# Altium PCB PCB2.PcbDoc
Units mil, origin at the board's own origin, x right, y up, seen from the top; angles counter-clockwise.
Board outline 2244.09 x 1732.28 mil, 4 copper layers (Top Layer, GND02, POWER03, Bottom Layer), stack 75.523 mil thick; 44 components, 99 nets, 307 pads, 120 vias.
Unrouted connection lines stored in the file: 48.
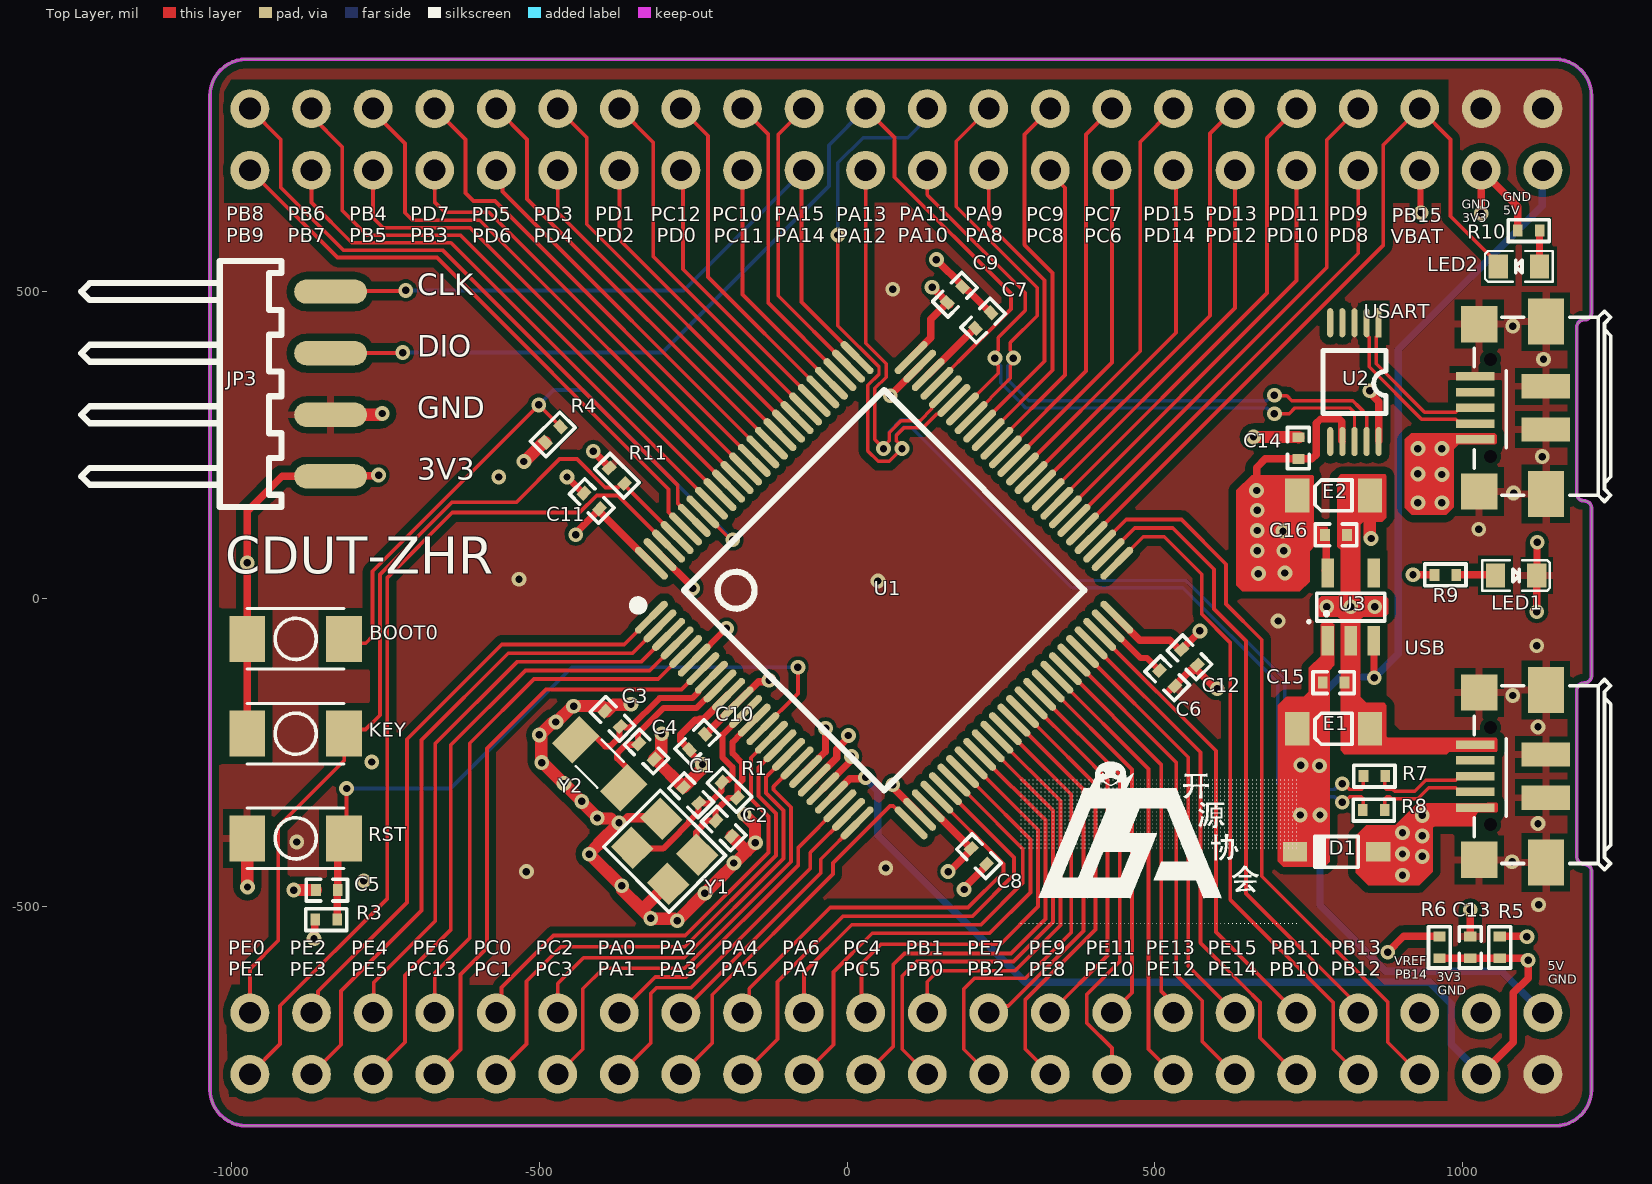
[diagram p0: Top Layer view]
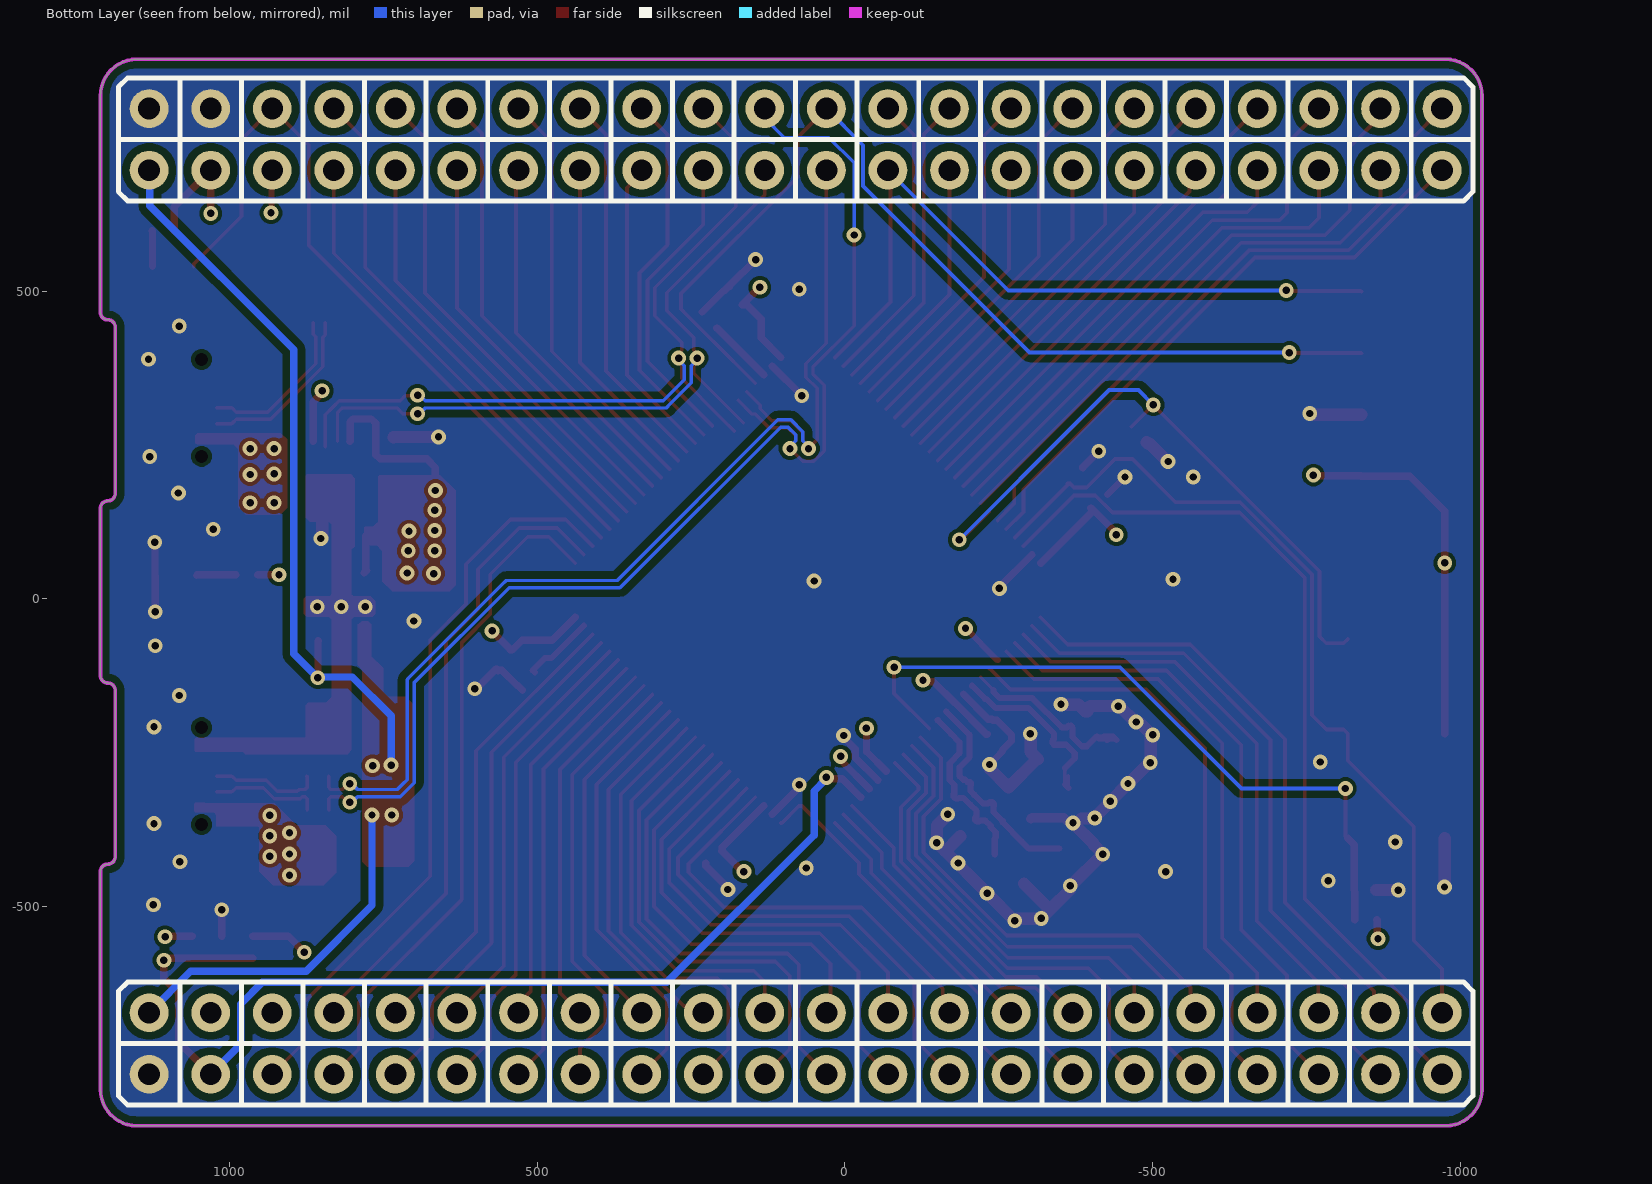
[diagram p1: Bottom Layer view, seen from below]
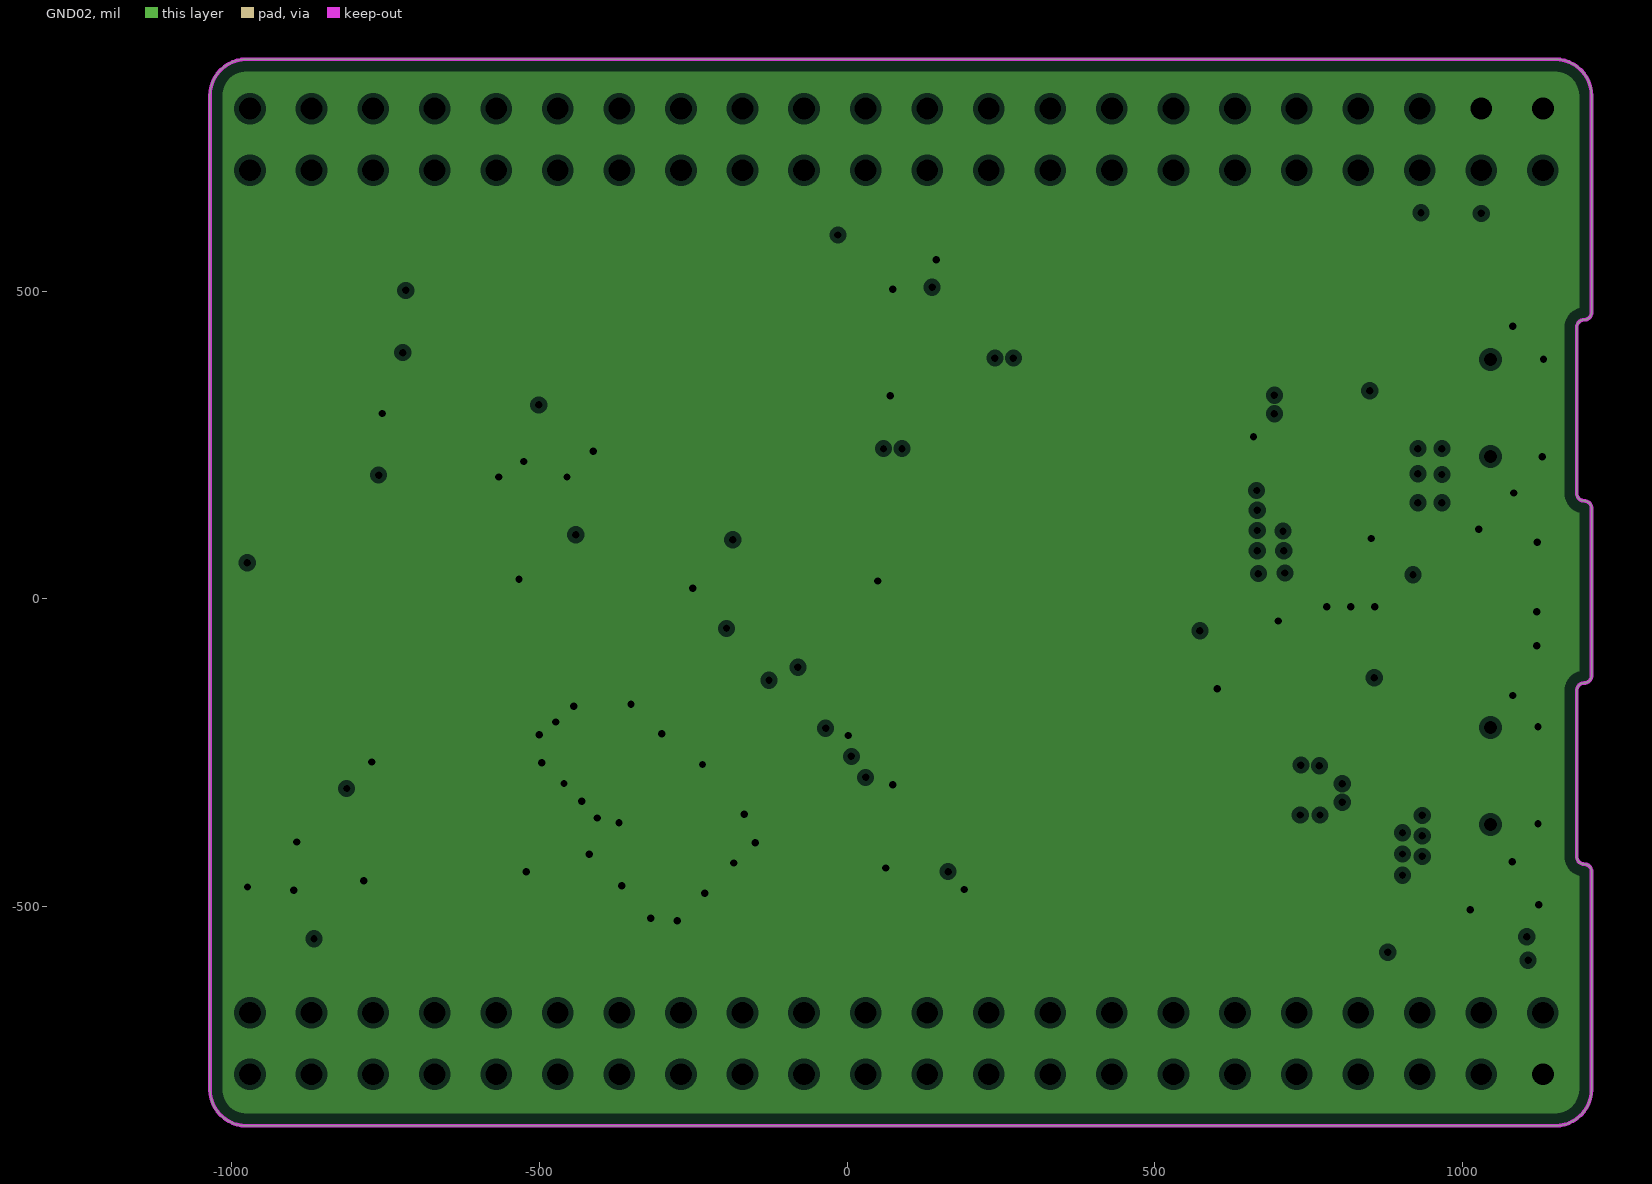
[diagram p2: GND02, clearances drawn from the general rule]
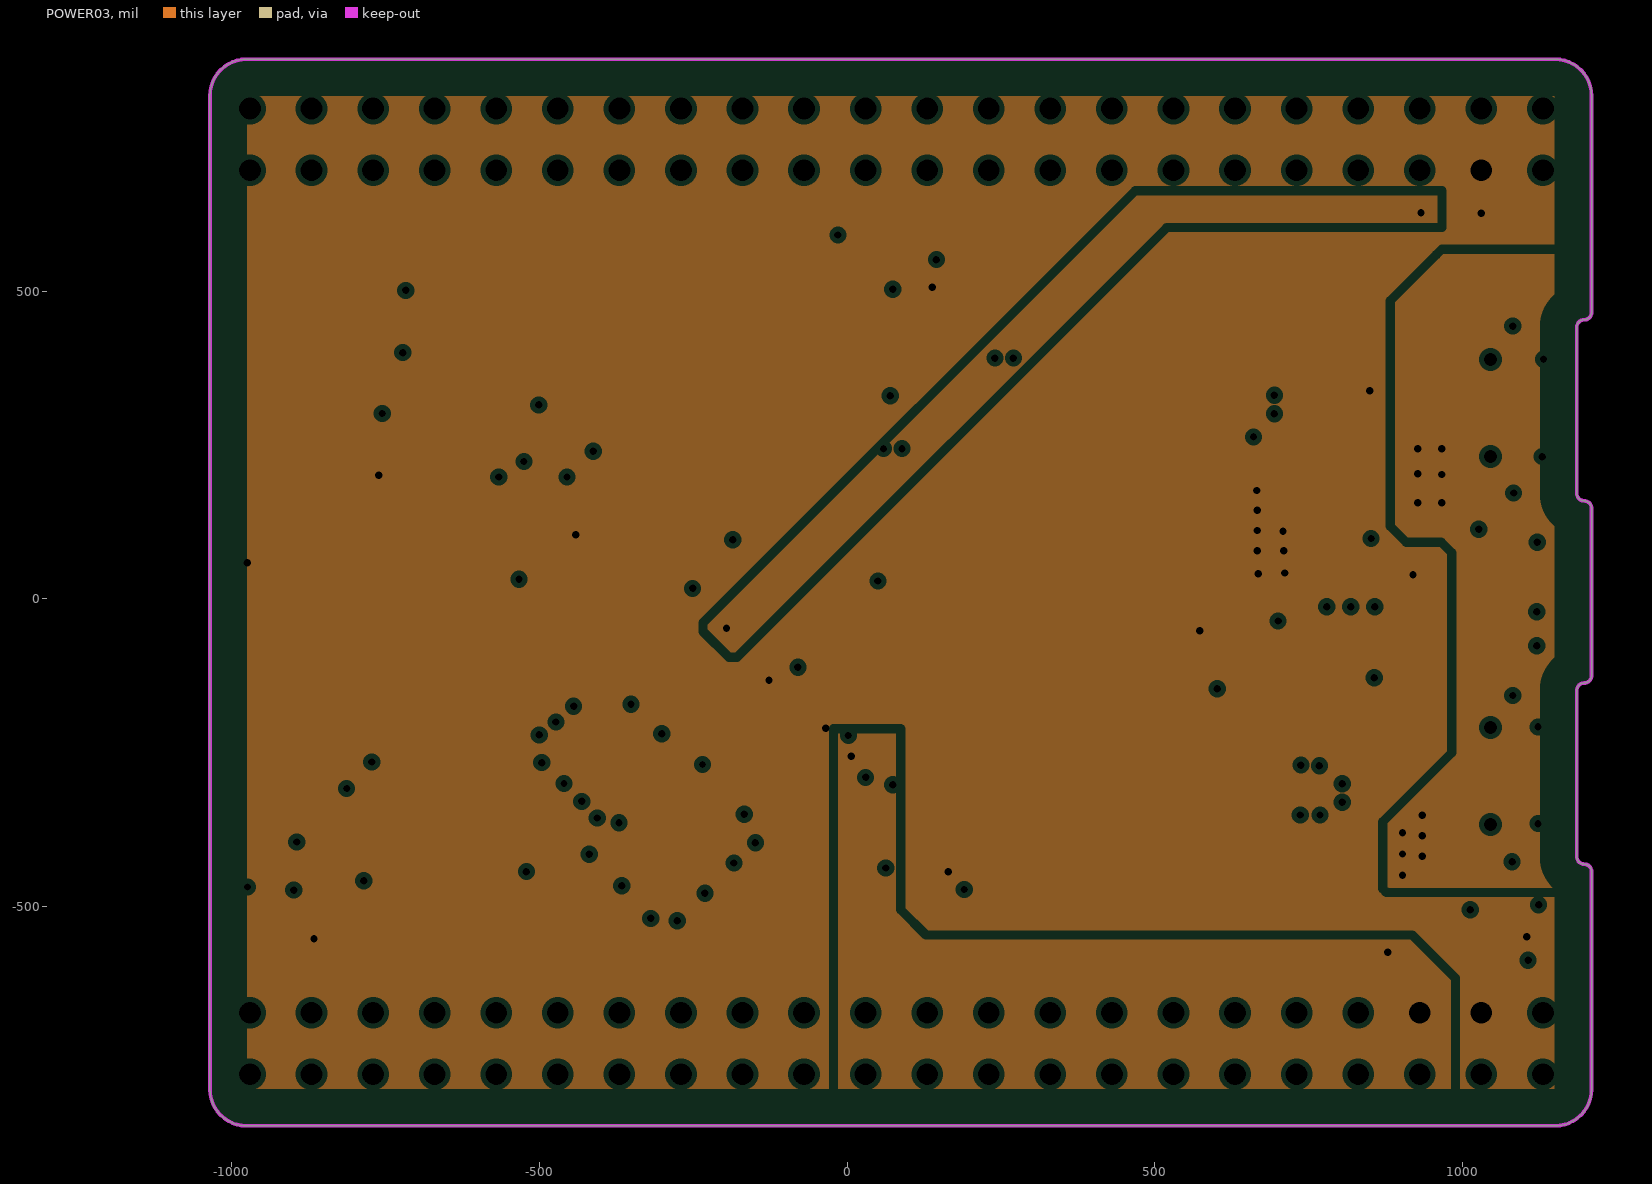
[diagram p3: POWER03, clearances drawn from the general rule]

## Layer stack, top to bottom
Top Solder: solder mask 0.4, Solder Resist, Dk 3.5
Top Layer: signal copper 1.38
Dielectric 2: prepreg 3.91, PP-015, Dk 4.3
GND02: plane copper 0.689, net GND
Dielectric 4: prepreg 2.8, PP-006, Dk 4.1
Dielectric 1: dielectric 2.8, FR-4, Dk 4.8
Dielectric 5: prepreg 2.8, PP-006, Dk 4.1
POWER03: plane copper 0.689, net (Multiple Nets)
Dielectric 3: prepreg 59.055, PP-006, Dk 4.1
Bottom Layer: signal copper 1.4
Bottom Solder: solder mask 0.4, Solder Resist, Dk 3.5

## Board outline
-1034.98,-796.8 ccw(c-975.92,-796.8) -975.93,-855.86 1150.06,-855.86 ccw(c1150.06,-796.8) 1209.11,-796.8 1209.11,-442.87 ccw(c1197.11,-442.87) 1197.11,-430.87 cw(c1197.11,-418.87) 1185.11,-418.87 1185.11,-148.71 cw(c1197.11,-148.71) 1197.11,-136.71 ccw(c1197.11,-124.71) 1209.11,-124.71 1209.11,147.13 ccw(c1197.11,147.13) 1197.11,159.13 cw(c1197.11,171.13) 1185.11,171.13 1185.11,441.29 cw(c1197.11,441.29) 1197.11,453.29 ccw(c1197.11,465.29) 1209.11,465.29 1209.11,817.37 ccw(c1150.06,817.37) 1150.06,876.43 -975.92,876.43 ccw(c-975.92,817.37) -1034.98,817.37

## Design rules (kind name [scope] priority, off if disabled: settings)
Clearance [All] p1: gap=6 ignorepadtopadclearanceinfootprint=FALSE except(12: Arc-Fill Arc-Poly Arc-Region Track-Fill Track-Poly Track-Region SMDPad-Fill SMDPad-Poly SMDPad-Region THPad-Fill THPad-Poly THPad-Region Fill-Fill Fill-Poly Fill-Region Poly-Poly Poly-Region Region-Region)
DiffPairsRouting DiffPair_DiffPairsRouting [All] p1: maxlimit=6 minlimit=6 mostfreqgap=6 toplayer_minwidth=5.59 toplayer_maxwidth=10 toplayer_prefwidth=5.59 bottomlayer_minwidth=5.59 bottomlayer_maxwidth=10 bottomlayer_prefwidth=5.59 maxuncoupledlength=500
DiffPairsRouting [All] p2: maxlimit=10 minlimit=10 mostfreqgap=10 toplayer_minwidth=15 toplayer_maxwidth=15 toplayer_prefwidth=15 bottomlayer_minwidth=15 bottomlayer_maxwidth=15 bottomlayer_prefwidth=15 maxuncoupledlength=500
Height [All] p1: minheight=0 maxheight=5000 prefheight=1000
MatchedLengths DiffPair_MatchedLengths [All] p1: tolerance=1000 checknetsindiffpair=FALSE checkdiffpairvsdiffpair=TRUE checkxsignals=TRUE checkothers=TRUE
PlaneClearance [All] p1: clearance=8
PlaneConnect [All] p1: pad.planeconnectstyle=Relief pad.reliefexpansion=12 pad.reliefentries=4 pad.reliefconductorwidth=10 pad.reliefairgap=8 via.planeconnectstyle=Direct via.reliefexpansion=20 via.reliefentries=4 via.reliefconductorwidth=10 via.reliefairgap=10
PolygonConnect [All] p1: thpad.connectstyle=Direct thpad.reliefconductorwidth=10 thpad.reliefentries=4 thpad.polygonreliefangle="90 Angle" thpad.airgapwidth=10 smdpad.connectstyle=Relief smdpad.reliefconductorwidth=12 smdpad.reliefentries=4 smdpad.polygonreliefangle="90 Angle" smdpad.airgapwidth=10 via.connectstyle=Direct via.reliefconductorwidth=10 via.reliefentries=4 via.polygonreliefangle="90 Angle" via.airgapwidth=10
RoutingVias [All] p1: holewidth=12 width=24 viastyle="Through Hole" minholewidth=12 minwidth=24 maxholewidth=12 maxwidth=24
SilkToSilkClearance [All] p1: silktosilkclearance=0
SilkToSolderMaskClearance [IsPad] p1: minsilkscreentomaskgap=4 clearancetoexposedcopper=TRUE
SolderMaskExpansion [All] p1: expansion=4 istentingtop=FALSE
SupplyNets "Schematic Supply Nets_3" [InNet('VCC')] p1: voltage=0.000
SupplyNets "Schematic Supply Nets_2" [InNet('3V3')] p2: voltage=0.000
SupplyNets "Schematic Supply Nets_1" [InNet('5V')] p3: voltage=0.000
SupplyNets "Schematic Supply Nets" [InNet('GND')] p4: voltage=0.000
UnRoutedNet [All] p1: checkbadconnections=TRUE
Width Width_power [InNetClass('power')] p1: maxlimit=100 minlimit=10 preferedwidth=12
Width [All] p2: maxlimit=100 minlimit=6.16 preferedwidth=6.16
23 further rules are at their usual default settings.

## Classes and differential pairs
net class power: 3V3 5V GND NetLED1_1 NetLED2_1 VBAT VCAP_1 VCAP_2 VCC VDDA VREF+
component class U_03-KEY+LED+SWD: BOOT0 C5 JP3 KEY LED1 LED2 R3 R4 R9 R10 R11 RST
component class U_02-CPU+Connect: C1 C2 C3 C4 C6 C7 C8 C9 C10 C11 C12 C13 R1 R5 R6 Y1 Y2
component class U_01-POWER: C14 C15 C16 D1 E1 E2 R8 U2 U3 USART USB
differential pair NewDifferentialPair6: +PA9 -PA10
differential pair NewDifferentialPair5: +PA11 -PA12
differential pair NewDifferentialPair4: +NetU2_1 -NetU2_2
differential pair NewDifferentialPair3: +NetR7_1 -NetR8_1
differential pair NewDifferentialPair2: +PH0 -PH1
differential pair NewDifferentialPair1: +PC14 -PC15

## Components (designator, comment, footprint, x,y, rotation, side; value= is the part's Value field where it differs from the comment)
BOOT0 "KEY" SWT3*4 -895.74,-65 r180 top (schematic designator KEY2)
C1 "20pF" "C 0402_L" -253.43,-318.89 r315 top
C2 "20pF" "C 0402_L" -200.43,-372.89 r135 top
C3 "10pF" "C 0402_L" -381,-195 r315 top
C4 "10pF" "C 0402_L" -326,-248 r135 top
C5 "0.1uF" "C 0402_L" -845,-473 r0 top
C6 "2.2uF" "C 0402_L" 520,-129 r135 top
C7 "2.2uF" "C 0402_L" 221,452 r225 top
C8 "0.1uF" "C 0402_L" 214,-418 r315 top
C9 "0.1uF" "C 0402_L" 175,494 r45 top
C10 "0.1uF" "C 0402_L" -243.53,-232.53 r225 top
C11 "0.1uF" "C 0402_L" -415,159 r135 top
C12 "0.1uF" "C 0402_L" 556,-95 r315 top
C13 "0.1uF" "C 0402_L" 1012,-566 r270 top
C14 "0.1uF" "C 0402_L" 733,245 r270 top
C15 "0.1uF" "C 0402_L" 790,-136 r180 top
C16 "0.1uF" "C 0402_L" 794,104 r180 top
D1 "1N4007" SOD-123 795,-411 r180 top
E1 "10uF" "CD A(3216)" 790,-211 r0 top
E2 "10uF" "CD A(3216)" 790,168 r0 top
JP1 "Header 2x22" HDR2.54-LI-2X22P 80,746.28 r180 top
JP2 "Header 2x22" HDR2.54-LI-2X22P 80,-722.22 r180 top
JP3 "SWD" HDR2.54-WS-4P -839,349 r90 top
KEY "KEY" SWT3*4 -895.74,-219 r180 top (schematic designator KEY3)
LED1 "LED" "LED 0603" 1086.46,38 r0 top
LED2 "LED" "LED 0603" 1091,540 r180 top
R1 "1M" "R 0402_L" -190.9,-310.42 r315 top
R3 "10K" "R 0402_L" -846,-521 r0 top
R4 "10K" "R 0402_L" -478,267 r45 top
R5 "0R" "R 0402_L" 1060,-566 r90 top
R6 "0R" "R 0402_L" 962,-566 r90 top
R7 "0R" "R 0402_L" 856.28,-288 r180 top
R8 "0R" "R 0402_L" 855.28,-343 r180 top
R9 "4.7K" "R 0402_L" 971.72,39 r0 top
R10 "4.7K" "R 0402_L" 1107,598 r0 top
R11 "10K" "R 0402_L" -374,200 r315 top
RST "KEY" SWT3*4 -895.74,-389 r180 top (schematic designator KEY1)
U1 "STM32F407VET6" "LQFP100 14X14_N" 60,14 r315 top
U2 "CH340E" MSOP10_L 824,352 r180 top
U3 "RT9013-33" SOT23-5N 817.94,-13 r0 top
USART "USB" USB-MICRO_E 1135,310.26 r90 top (schematic designator USB1)
USB "USB" USB-MICRO_E 1135,-288 r90 top (schematic designator USB2)
Y1 "8M" "OSC 3225-4P" -296.43,-409.89 r315 top
Y2 "32.768KHz" FC135-3.2X1.5 -402,-268 r315 top

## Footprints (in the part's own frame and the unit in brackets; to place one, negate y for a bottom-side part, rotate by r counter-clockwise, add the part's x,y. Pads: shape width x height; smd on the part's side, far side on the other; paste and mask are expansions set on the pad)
"C 0402_L" [mm] "无极性贴片电容"
  rect 0.4x0.5 smd: 1(-0.45,0) 2(0.45,0)
  silkscreen extent -0.85,-0.45 0.85,0.45, body extent -0.5,-0.26 0.5,0.26, height 0.53
"CD A(3216)" [mm] "长3.2mm，宽1.6mm，厚1.6mm"
  rect 1x1.4 smd: 1(-1.5,0) 2(1.5,0)
  silkscreen extent -0.76,-0.64 0.76,0.64, body extent -1.6,-0.8 1.6,0.8, height 1.6
FC135-3.2X1.5 [mm] "晶振"
  rect 1.2x1.6 smd: 1(-1.4,0) 2(1.4,0)
  silkscreen extent -0.64,-0.76 0.64,0.76, body extent -1.61,-0.76 1.61,0.76, height 0.91
HDR2.54-LI-2X22P [mm] "双排排针，20x2脚"
  round 1.6 hole 0.9: 1(-26.67,-1.27) 2(-26.67,1.27) 3(-24.13,-1.27) 4(-24.13,1.27) 5(-21.59,-1.27) 6(-21.59,1.27) 7(-19.05,-1.27) 8(-19.05,1.27) 9(-16.51,-1.27) 10(-16.51,1.27) 11(-13.97,-1.27) 12(-13.97,1.27) 13(-11.43,-1.27) 14(-11.43,1.27) 15(-8.89,-1.27) 16(-8.89,1.27) 17(-6.35,-1.27) 18(-6.35,1.27) 19(-3.81,-1.27) 20(-3.81,1.27) 21(-1.27,-1.27) 22(-1.27,1.27) 23(1.27,-1.27) 24(1.27,1.27) 25(3.81,-1.27) 26(3.81,1.27) 27(6.35,-1.27) 28(6.35,1.27) 29(8.89,-1.27) 30(8.89,1.27) 31(11.43,-1.27) 32(11.43,1.27) 33(13.97,-1.27) 34(13.97,1.27) 35(16.51,-1.27) 36(16.51,1.27) 37(19.05,-1.27) 38(19.05,1.27) 39(21.59,-1.27) 40(21.59,1.27) 41(24.13,-1.27) 42(24.13,1.27) 43(26.67,-1.27) 44(26.67,1.27)
  body extent -27.94,-2.54 27.94,2.54, height 8.5
HDR2.54-WS-4P [mm] "4P卧式贴片排针2.54"
  oval 1x3 smd: 1(-3.81,0) 2(-1.27,0) 3(1.27,0) 4(3.81,0)
  silkscreen extent -5.08,2.03 5.08,10.29, body extent -5.08,-0.76 5.08,10.34, height 2.54
"LED 0603" [mm] "贴片带丝印"
  rect 0.8x1 smd: 1(-0.85,0) 2(0.85,0)
  silkscreen extent -1.4,-0.64 1.4,0.64, body extent -0.8,-0.4 0.8,0.4, height 0.61
"LQFP100 14X14_N" [mm] "100脚，体宽14x14mm，脚距0.5mm"
  oval 0.3x1.8 smd: 1(-6,-7.575) 2(-5.5,-7.575) 3(-5,-7.575) 4(-4.5,-7.575) 5(-4,-7.575) 6(-3.5,-7.575) 7(-3,-7.575) 8(-2.5,-7.575) 9(-2,-7.575) 10(-1.5,-7.575) 11(-1,-7.575) 12(-0.5,-7.575) 13(0,-7.575) 14(0.5,-7.575) 15(1,-7.575) 16(1.5,-7.575) 17(2,-7.575) 18(2.5,-7.575) 19(3,-7.575) 20(3.5,-7.575) 21(4,-7.575) 22(4.5,-7.575) 23(5,-7.575) 24(5.5,-7.575) 25(6,-7.575) 51(6,7.575) 52(5.5,7.575) 53(5,7.575) 54(4.5,7.575) 55(4,7.575) 56(3.5,7.575) 57(3,7.575) 58(2.5,7.575) 59(2,7.575) 60(1.5,7.575) 61(1,7.575) 62(0.5,7.575) 63(0,7.575) 64(-0.5,7.575) 65(-1,7.575) 66(-1.5,7.575) 67(-2,7.575) 68(-2.5,7.575) 69(-3,7.575) 70(-3.5,7.575) 71(-4,7.575) 72(-4.5,7.575) 73(-5,7.575) 74(-5.5,7.575) 75(-6,7.575)
  oval 1.8x0.3 smd: 26(7.576,-6) 27(7.576,-5.5) 28(7.576,-5) 29(7.576,-4.5) 30(7.576,-4) 31(7.576,-3.5) 32(7.576,-3) 33(7.576,-2.5) 34(7.576,-2) 35(7.576,-1.5) 36(7.576,-1) 37(7.576,-0.5) 38(7.576,0) 39(7.576,0.5) 40(7.576,1) 41(7.576,1.5) 42(7.576,2) 43(7.576,2.5) 44(7.576,3) 45(7.576,3.5) 46(7.576,4) 47(7.576,4.5) 48(7.576,5) 49(7.576,5.5) 50(7.576,6) 76(-7.575,6) 77(-7.575,5.5) 78(-7.575,5) 79(-7.575,4.5) 80(-7.575,4) 81(-7.575,3.5) 82(-7.575,3) 83(-7.575,2.5) 84(-7.575,2) 85(-7.575,1.5) 86(-7.575,1) 87(-7.575,0.5) 88(-7.575,0) 89(-7.575,-0.5) 90(-7.575,-1) 91(-7.575,-1.5) 92(-7.575,-2) 93(-7.575,-2.5) 94(-7.575,-3) 95(-7.575,-3.5) 96(-7.575,-4) 97(-7.575,-4.5) 98(-7.575,-5) 99(-7.575,-5.5) 100(-7.575,-6)
  silkscreen extent -6.92,-7.81 5.84,5.84, body extent -8,-8 8,8, height 1.45
MSOP10_L [mm] "塑封体长3mm，宽3mm，脚距0.5"
  rect 0.25x1.2 smd: 1(-1,-2.45)
  oval 0.25x1.2 smd: 2(-0.5,-2.45) 3(0,-2.45) 4(0.5,-2.45) 5(1,-2.45) 6(1,2.45) 7(0.5,2.45) 8(0,2.45) 9(-0.5,2.45) 10(-1,2.45)
  silkscreen extent -1.3,-1.3 1.3,1.3, body extent -1.5,-2.45 1.5,2.45, height 0.95
"OSC 3225-4P" [mm] "3.2*2.5*0.7mm(长宽高)"
  rect 1.3x1.2 smd: 1(-1.05,-0.85) 2(1.05,-0.85) 3(1.05,0.85) 4(-1.05,0.85)
  silkscreen extent -1.9,-1.65 1.9,1.65, body extent -1.6,-1.25 1.6,1.25, height 0.7
"R 0402_L" [mm] "1/16W贴片电阻"
  rect 0.4x0.5 smd: 1(-0.45,0) 2(0.45,0)
  silkscreen extent -0.85,-0.45 0.85,0.45, body extent -0.5,-0.25 0.5,0.25, height 0.3
SOD-123 [mm] "2.7x1.6X1.1mm（长宽高，不包括引脚）"
  rect 1x0.8 smd: 1(-1.714,0) 2(1.714,0)
  silkscreen extent -0.89,-0.64 0.89,0.64, body extent -1.85,-0.8 1.85,0.8, height 1.22
SOT23-5N [mm] "3x1.6x1.1mm(长宽高)"
  rect 0.5x1.2 smd: 1(-0.95,-1.4) 2(0,-1.4) 3(0.95,-1.4) 4(0.95,1.4) 5(-0.95,1.4)
  silkscreen extent -1.4,-0.58 1.4,0.56, body extent -1.45,-1.4 1.45,1.4, height 1.2
SWT3*4 [mm]
  rect 1.48x1.9 smd: 1(-2,0) 2(2,0)
  silkscreen extent -2,-1.25 2,1.25, body extent -2.45,-1.45 2.45,1.45, height 2
USB-MICRO_E [mm] "micro型USB ，5.9*8.2*2.5mm"
  round 0 hole 0.54 unplated: 0(-2,2.294) 0(2,2.294)
  rect 0.35x1.6 smd: 1(-1.295,2.921) 2(-0.648,2.921) 3(0,2.921) 4(0.648,2.921) 5(1.295,2.921)
  rect 1.9x1.5 smd: 5(-3.556,0) 5(3.556,0)
  rect 1.5x1.5 smd: 5(-3.454,2.754) 5(3.454,2.754)
  rect 1x2 smd: 5(-0.889,0.01) 5(0.889,0.01)
  silkscreen extent -3.86,-2.67 3.99,2.96, body extent -4,-2.72 4,3.36, height 2.8

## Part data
C1 C2 C3 C4 C5 C6 C7 C8 C9 C10 C11 C12 C13 C14 C15 C16: library part Cap
D1: "整流二极管"
E1 E2: library part C-CD, "贴片钽电容"
JP1 JP2: "2x22P接插件"
JP3: library part "Header 1*4"
R1 R3 R4 R5 R6 R7 R8 R9 R10 R11: library part Res
U1: BOM_Manufacturer=ST
Y1: library part XTAL-4P, "4脚无源晶振"
Y2: library part XTAL-2P

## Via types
v1: diameter 24, hole 12, Top Layer to Bottom Layer, 120 vias

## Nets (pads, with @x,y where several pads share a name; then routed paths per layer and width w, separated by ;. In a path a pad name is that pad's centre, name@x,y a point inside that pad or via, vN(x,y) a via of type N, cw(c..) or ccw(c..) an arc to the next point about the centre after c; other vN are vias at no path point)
3V3: BOOT0.2 C8.1 C9.1 C10.1 C11.1 C12.1 C14.2 C16.2 E2.1 JP1.4 JP2.3 JP3.1 KEY.2 R3.1 R5.2 R9.1 R10.1 U1.11 U1.19 U1.28 U1.50 U1.75 U1.100 U2.7 U2.10 U3.5 | length 2271.2
  Top Layer w12: KEY.2 BOOT0.2 -974.48,142.52 -918,199 JP3.1 -838,200 -762,200 v1(-761,201) ; v1(-866,-552) -864.86,-550.86 -864.86,-522.14 R3.1 ; v1(-441,104) -441,106.97 -400.5,147.47 -399.47,147.47 -400.86,146.08 -400.86,140.8 U1.100 ; C10.1 -229.8,-220 -178.86,-169.06 -178.59,-169.06 -143.91,-134.38 -129.3,-134.38 v1(-127,-132.08) ; U1.19 -67.37,-280.28 -35.12,-248.03 -35.12,-210.12 v1(-35,-210) ; U1.75 136,424.06 136,454 159.5,477.5 166.47,477.5 v1(138,505.97) ; U1.28 199,-403.39 C8.1@199,-404 ; v1(164,-443) 165.97,-443 199.77,-409.2 C8.1@198.78,-408.22 ; U1.50 475.07,-67 524.27,-67 540.28,-83.01 543.28,-83.01 C12.1@543.86,-82.43 ; C12.1@544.34,-81.14 573,-52.47 v1(573,-52) ; v1(665,176) 665,213.26 679.03,227.29 C14.2 754.68,227.29 761.71,234.32 761.71,285.14 768.74,292.17 799.08,292.17 803.24,288.01 803.24,256.62 U2.7 ; 675,169 676,168 E2.1 ; C16.2@770.41,102.13 C16.2@772.29,104 ; C16.2 778,102.29 U3.5@778,44.66 ; U3.5@776.7,45.96 U3.5@778,44.66 ; U3.5 U3.5@778,44.66 ; v1(849,338) 849,334.75 863.37,320.38 U2.10 ; v1(919,39) R9.1 ; v1(1030,626) JP1.4 1089.28,637 R10.1 ; R5.2 1103.29,-548.29 v1(1104,-549)
  other v1: 668,41 711,42 -974.4,58.45 666,78 709,78 708,110 666,111 666,144
5V: C15.2 D1.2 E1.1 JP1.2 JP2.1 U3.1 U3.3 | length 1982
  Top Layer w12: E1.1 730.94,-174.03 737.97,-167 760,-167 770.41,-156.59 770.41,-137.87 C15.2 772.29,-114.71 781,-106 781,-68.58 U3.1 U3.1@780,-67.58 ; U3.3 855.67,-68.45 855.67,-127.67 v1(856,-128)
  Bottom Layer w12: v1(737,-270) 737,-190 800,-127 855,-127 v1(856,-128) 895,-89 895,405 1128.79,638.79 1128.79,695.07 JP1.2 ; v1(768,-351) 768,-497.94 875.06,-605 1062.78,-605 JP2.1
  other v1: 736,-351 767,-271
BOOT0: BOOT0.1 R4.2 U1.94 | length 1084.3
  Top Layer w6.16: BOOT0.1 -810,-72 -782,-72 -771.16,-61.16 -771.16,44.84 v1(-501,315) ; v1(-501,315) R4.2 ; U1.94 -189.03,96 v1(-186,96)
  Bottom Layer w6.16: v1(-501,315) -477,339 -429,339 -383,293 v1(-186,96)
GND: C1.1 C2.1 C3.1 C4.1 C5.1 C6.1 C7.1 C8.2 C9.2 C10.2 C11.2 C12.2 C13.1 C14.1 C15.1 C16.1 E1.2 E2.2 JP1.1 JP1.3 JP2.2 JP3.2 LED1.2 R4.1 R11.1 RST.2 U1.10 U1.20 U1.27 U1.74 U1.99 U2.3 U3.2 USART.5 USB.5 Y1.2 Y1.4 | length 2593.2
  Top Layer w12: v1(-455,197.97) C11.2@-426.53,169.5 ; v1(-412.41,239.75) -412.41,239.5 -386.53,213.61 R11.1 ; U1.99 -304,71.64 -251,18.64 v1(-251,17) ; v1(-235,-269) -252.01,-251.99 -252.01,-251.74 -256.05,-247.7 C10.2 -270.66,-230.45 -270.66,-220.51 -247.23,-197.08 -240.91,-197.08 -239.3,-195.47 -232.98,-195.47 U1.10 ; U1.20 -17.12,-258.01 -17.12,-244.37 2,-225.25 v1(2,-222) ; v1(70,330) 70,330.22 U1.74 ; v1(74,-302) 76.3,-304.3 76.3,-308.52 U1.27 ; v1(145,551) 187.53,508.47 C9.2 190.18,506.52 195.98,500.72 197.1,500.72 C7.1@231.91,465.92 ; v1(190,-472) 190,-469.53 225.82,-433.7 C8.2@225.82,-429.32 ; 523.53,-148.53 531.24,-140.81 532.24,-140.81 557.14,-115.92 562.55,-115.92 563.13,-116.5 565.03,-114.6 567.1,-114.6 598.5,-146 v1(601,-146) ; C13.1 v1(1012,-505) ; v1(1120,-21) v1(1120,-21) 1119.96,37.96 LED1.2 1120.46,38.54 1120.46,91.46 v1(1121,92)
  Top Layer w15: v1(-370.49,-363.85) -368.77,-362.13 -362.41,-362.13 -355.89,-355.61 -303.39,-355.61 Y1.4
  Top Layer w20: RST.2 -974.48,-467.52 v1(-974,-468) ; v1(-899,-473) C5.1 ; JP3.2 -758.08,299 -756.08,301 v1(-755,301) ; v1(-525,223) -523.92,223 -494.87,252.05 -492.95,252.05 R4.1 ; v1@-444.33,-175 v1@-443.38,-174.05 ; v1@-442.99,-173.65 v1@-443.38,-174.05 ; C3.1 C3.1@-390,-182.47 ; -383.98,-356.77 -405.23,-356.77 v1(-406,-356) -406,-355 -431,-330 v1(-431,-329) -460.77,-299.23 -461.77,-299.23 -495,-266 v1(-496,-266) -496.77,-265.23 -496.77,-225.32 -500,-222.08 v1(-500,-221) -498.92,-221 -478.68,-200.77 -473.77,-200.77 v1(-473,-200) -471.92,-200 -447.1,-175.18 -445.1,-175.18 v1(-444.33,-174.42) -443.96,-174.05 v1@-443.38,-174.05 ; v1(-370.49,-363.85) -370.49,-364.49 -404.44,-398.44 -404.44,-399.36 -419,-413.92 v1(-419,-415) -418,-415 -367.25,-465.75 -366,-465.75 -365.23,-466.52 -365.23,-472.77 -334,-504 ; v1(-351,-171.08) -351.77,-171.85 -379.37,-171.85 C3.1@-390,-182.47 ; v1(-301,-219) -301.77,-219.77 -301.77,-248.82 C4.1 -311.8,-260.53 C1.1 -236.31,-276.71 -236.31,-270.31 v1(-235,-269) ; Y1.2 -332.08,-504 -334,-504 ; C2.1 -163.33,-410 -163,-410 ; v1(-167,-350) -167,-351.08 -149.77,-368.32 -149.77,-395.23 v1(-149,-396) -163,-410 ; v1(660,263) 732.72,263 C14.1 ; E2.2 849.06,101.03 851,99.08 v1(851,98) ; v1@-443.38,-174.05 -398.42,-174.05 C3.1@-390,-182.47 ; -334,-504 v1(-319,-519) -318.23,-519.77 -280.32,-519.77 -277.08,-523 v1(-276,-523) v1(-231,-478) -163,-410
  other v1: 1123,-497 -366,-466 -785,-458 -521,-443 62.8,-437.07 -184,-429 1080,-427 -894,-395 1122,-365 -460,-300 -772,-265 1122,-208 1081,-157 1120,-76 700,-36 779,-12.83 818,-12.83 857,-12.83 50,29 -533,32 1026,113 1082.51,171.84 -566,198 1129,231 1131,389 1081,443 74,503
NetLED1_1: LED1.1 R9.2 | length 64
  Top Layer w12: R9.2 1052,39 LED1.1
NetLED2_1: LED2.1 R10.2 | length 58.1
  Top Layer w12: LED2.1 1124.59,540.12 1124.59,597.87 R10.2
NetR7_1: R7.1 USB.3 | length 178.1
  Top Layer w5.59: R7.1 873.5,-288.5 873.5,-306.43 876.77,-309.7 886.4,-309.7 889.5,-312.8 921.8,-312.8 939.65,-294.95 988.44,-294.95 995.39,-288 USB.3
NetR8_1: R8.1 USB.2 | length 178.1
  Top Layer w5.59: R8.1 873.3,-342.7 873.3,-324.77 876.77,-321.3 881.6,-321.3 884.7,-324.39 926.61,-324.39 944.45,-306.55 988.44,-306.55 995.39,-313.5 USB.2
NetU2_1: U2.1 USART.3 | length 264.5
  Top Layer w5.59: U2.1 863.37,429.76 859.32,425.71 859.32,381.68 937.7,303.3 988.44,303.3 995.39,310.26 USART.3
NetU2_2: U2.2 USART.2 | length 283.7
  Top Layer w5.59: U2.2 843.69,428.61 847.73,424.56 847.73,376.88 932.89,291.71 988.44,291.71 995.39,284.76 USART.2
NRST: C5.2 R3.2 RST.1 U1.14 | length 1154.6
  Top Layer w6.16: RST.1 -813,-385 v1(-813,-308) ; U1.14 -80,-153.85 v1(-80,-111)
  Top Layer w12: R3.2 C5.2@-828.29,-475.36 ; C5.2 -827.29,-399.29 RST.1
  Bottom Layer w6.16: v1(-813,-308) -644,-308 -447,-111 v1(-80,-111)
PA0: JP2.31 U1.23 | length 514.2
  Top Layer w6.16: JP2.31 -311.78,-614 -261.21,-614 -79.28,-432.07 -79.28,-403.68 U1.23
PA1: JP2.32 U1.24 | length 609.2
  Top Layer w6.16: JP2.32 -319,-721.22 -319,-641 -309.64,-631.64 -253.64,-631.64 -60,-438 -60,-412.24 U1.24
PA2: JP2.29 U1.25 | length 426.8
  Top Layer w6.16: JP2.29 -43,-445.22 -43,-423.08 U1.25
PA3: JP2.30 U1.26 | length 622.2
  Top Layer w6.16: JP2.30 -219,-721.22 -219,-643 -23,-447 -23,-429 69.65,-336.35 74.75,-336.35 102.33,-363.93 U1.26
PA4: JP2.27 U1.29 | length 701.8
  Top Layer w6.16: JP2.27 -159.13,-661.35 -159.13,-633.13 -43,-517 -27.5,-501.5 196.5,-501.5 254,-444 254,-430.55 U1.29
PA5: JP2.28 U1.30 | length 815.9
  Top Layer w6.16: JP2.28 -113,-715.22 -113,-621.84 -6.58,-515.42 203.42,-515.42 271.14,-447.69 271.14,-426.82 271.14,-419.86 186.77,-335.48 U1.30
PA6: JP2.25 U1.31 | length 694.2
  Top Layer w6.16: JP2.25 -70,-606.68 7.34,-529.34 217.34,-529.34 285.06,-461.61 285.06,-405.94 200.69,-321.56 U1.31
PA7: JP2.26 U1.32 | length 801.4
  Top Layer w6.16: JP2.26 -22,-724.22 -22,-606 40.74,-543.26 231.26,-543.26 297.68,-476.84 297.68,-390.71 214.61,-307.64 U1.32
PA8: JP1.20 U1.67 | length 496.8
  Top Layer w6.16: U1.67 320.51,385.86 320.51,517.49 230,608 JP1.20
PA9: JP1.19 U1.68 U2.9 | length 1362.6
  Top Layer w5.59: U1.68@179.23,272.41 U1.68 264.84,358.03 264.84,378.52 266.48,380.16 266.48,388.59 v1@268.89,391 ; JP1.19 177,743.28 177,636.84 308.64,505.2 308.64,460.16 264.84,416.36 264.84,403.48 266.48,401.84 266.48,394.52 v1(270,391) ; v1(694,330.8) 695.14,329.66 714.39,329.66 722.45,321.59 821.41,321.59 832.2,310.8 843.69,299.32 U2.9 U2.9@843.69,247.32
  Bottom Layer w5.59: v1(270,391) 270,387.73 260.8,378.52 260.8,355.99 295.19,321.59 681.52,321.59 690.73,330.8 v1(694,330.8)
PA10: JP1.22 U1.69 U2.8 | length 1226.3
  Top Layer w5.59: JP1.22@124.84,695.95 130,690.78 130,656 157.32,628.69 288.95,497.05 288.95,468.31 245.16,424.51 245.16,403.48 243.52,401.84 243.52,394.52 v1(240,391) 243.52,387.48 243.52,380.16 245.16,378.52 245.16,366.18 U1.69@165.31,286.33 ; v1(694,300.8) 718.05,300.8 727.26,310 816.61,310 820.61,306 824,302.61 U2.8
  Bottom Layer w5.59: v1(240,391) 240,387.73 249.2,378.52 249.2,351.19 255.99,344.4 283.6,316.79 290.39,310 681.52,310 690.73,300.8 v1(694,300.8)
PA11: JP1.21 R8.2 U1.70 | length 2068.7
  Top Layer w5.59: v1(-15,591) -15,443.86 51.73,377.13 51.73,364.95 33.41,346.63 33.41,240.18 50.39,223.2 68.2,223.2 v1(89,244) 89,247.27 79.8,256.48 79.8,265.33 92.27,277.81 123.22,277.81 145.67,300.25 151.39,300.25 U1.70 ; v1(804,-330.5) 807.27,-330.5 816.48,-321.29 834.8,-321.29 838.07,-324.57 838.07,-342.5 R8.2
  Bottom Layer w5.59: v1(-15,591) -15,708.26 25.87,749.14 98.14,749.14 130,781 JP1.21 ; v1(89,244) 89,247.27 79.8,256.48 79.8,266.52 92.27,279 104.4,279 365.2,18.2 545.4,18.2 699.41,-135.8 699.41,-298.52 706.08,-305.19 722.18,-321.29 791.52,-321.29 800.73,-330.5 v1(804,-330.5)
PA12: JP1.24 R7.2 U1.71 | length 1811.2
  Top Layer w5.59: JP1.24 30,415.25 63.32,381.93 63.32,360.15 45,341.83 45,258.83 v1@59,244.83 ; v1(59,244) v1@59,244.83 ; U1.71 137.47,314.17 137.47,308.45 118.42,289.4 87.47,289.4 68.2,270.13 68.2,256.48 59,247.27 v1@59,244.83 ; v1(804,-300.5) 807.27,-300.5 816.48,-309.7 834.8,-309.7 838.27,-306.22 838.27,-288.29 R7.2
  Bottom Layer w5.59: v1(59,244) 59,247.27 68.2,256.48 68.2,271.32 87.47,290.59 109.2,290.59 370,29.8 550.2,29.8 556.99,23.01 613.08,-33.09 707.61,-127.61 711,-131 711,-293.72 717.67,-300.39 726.99,-309.7 791.52,-309.7 800.73,-300.5 v1(804,-300.5)
PA13: JP1.23 JP3.3 U1.72 | length 1666.3
  Top Layer w6.16: JP3.3 -838.5,399.5 -722.5,399.5 v1(-722,400) ; JP1.23 77.03,749.25 77.03,684.84 266,495.88 266,470.54 255.14,459.68 255.14,459.37 213.63,417.87 213.33,417.87 U1.72
  Bottom Layer w6.16: v1(-722,400) -300,400 -29.42,670.58 -29.42,736.86 JP1.23
PA14: JP1.26 JP3.4 U1.76 | length 1194.1
  Top Layer w6.16: JP3.4 -838,500 -718,500 v1(-717,501) ; JP1.26 -74,692.28 -74,482.07 U1.76
  Bottom Layer w6.16: v1(-717,501) -265.28,501 JP1.26
PA15: JP1.25 U1.77 | length 483
  Top Layer w6.16: JP1.25 -112,754.28 -112,492.23 U1.77
PB0: JP2.22 U1.35 | length 787.3
  Top Layer w6.16: JP2.22 89.42,-731.64 89.42,-612.58 113,-589 270.2,-589 334.16,-525.04 334.16,-343.68 U1.35
PB1: JP2.21 U1.36 | length 652.7
  Top Layer w6.16: JP2.21 130,-622 148,-604 272.39,-604 346.32,-530.07 346.32,-328 U1.36
PB2: JP2.20 U1.37 | length 743.4
  Top Layer w6.16: JP2.20 189.42,-731.64 189.42,-633.58 206.84,-616.16 289.64,-616.16 364,-541.8 364,-317.84 284.21,-238.05 U1.37
PB3: JP1.38 U1.89 | length 736.5
  Top Layer w6.16: JP1.38 -670,644.52 -653.48,628 -581.84,628 -314.92,361.08 U1.89
PB4: JP1.39 U1.90 | length 908.2
  Top Layer w6.16: JP1.39 -770,791.78 -718,739.78 -718,627 -706,615 -596.68,615 U1.90
PB5: JP1.40 U1.91 | length 835.2
  Top Layer w6.16: JP1.40 -770,619 -753.84,602.84 -612.36,602.84 U1.91
PB6: JP1.41 U1.92 | length 990.7
  Top Layer w6.16: JP1.41 -870,784 -820,734 -820,631 -779.68,590.68 -628.04,590.68 U1.92
PB7: JP1.42 U1.93 | length 904.2
  Top Layer w6.16: JP1.42 -870,644 -804.52,578.52 -643.71,578.52 U1.93
PB8: JP1.43 U1.95 | length 1062.1
  Top Layer w6.16: JP1.43 -920,746.28 -920,668 -818.36,566.36 -657.36,566.36 -275,184 -275,154.76 -248.32,128.09 U1.95
PB9: JP1.44 U1.96 | length 970.6
  Top Layer w6.16: JP1.44 -827.92,554.2 -666.2,554.2 -290,178 -290,141.29 U1.96
PB10: JP2.10 U1.47 | length 838.9
  Top Layer w6.16: U1.47 573.74,-249.19 573.74,-558.74 656.45,-641.45 cw(c630,-672.22) 660.77,-645.77 670.58,-655.58 670.58,-712.8 JP2.10
PB11: JP2.9 U1.48 | length 747
  Top Layer w6.16: U1.48 599,-246.61 599,-541.22 JP2.9
PB12: JP2.8 U1.51 | length 1098.6
  Top Layer w6.16: U1.51 481.04,100.96 515.04,100.96 576,40 576,-24.68 622.08,-70.76 622.08,-488.08 789.42,-655.42 789.42,-731.64 JP2.8
PB13: JP2.7 U1.52 | length 1034.6
  Top Layer w6.16: U1.52 467.12,114.88 528.96,114.88 595.69,48.15 595.69,-16.52 647.64,-68.48 647.64,-478.64 830,-661 JP2.7
PB14: JP2.6 U1.53 | length 1212
  Top Layer w6.16: U1.53 453.2,128.8 542.88,128.8 615.37,56.31 615.37,-8.37 673.52,-66.52 673.52,-450.52 878,-655 878,-720.22 JP2.6
PB15: JP1.5 LED2.2 U1.54 | length 1226.9
  Top Layer w6.16: U1.54 870.58,574.02 870.58,736.86 JP1.5 980,746.28 980,621.47 1057.54,543.94 LED2.2
PC0: JP2.35 U1.15 | length 781.5
  Top Layer w6.16: JP2.35 -561.48,-663.7 -561.48,-631.48 -477,-547 -263,-547 -127.92,-411.92 -127.92,-353.67 -156.33,-325.26 -156.33,-258.01 U1.15
PC1: JP2.36 U1.16 | length 865.8
  Top Layer w6.16: JP2.36 -521,-723.22 -521,-621.16 -464.84,-565 -263.8,-565 -115.76,-416.96 -115.76,-348.63 -144.17,-320.23 -144.17,-273.69 U1.16
PC2: JP2.33 U1.17 | length 694.1
  Top Layer w6.16: JP2.33 -470,-625 -428,-583 -264.61,-583 -103.6,-421.99 -103.6,-343.6 -132.01,-315.19 -132.01,-289.37 U1.17
PC3: JP2.34 U1.18 | length 767.4
  Top Layer w6.16: JP2.34 -429.42,-731.64 -429.42,-633.42 -396,-600 -264.41,-600 -91.44,-427.03 -91.44,-338.56 -119.85,-310.15 -119.85,-305.05 U1.18
PC4: JP2.23 U1.33 | length 685.6
  Top Layer w6.16: JP2.23 23.38,-665.6 23.38,-592.62 55.12,-560.88 248.88,-560.88 309.84,-499.92 309.84,-375.03 228.53,-293.72 U1.33
PC5: JP2.24 U1.34 | length 786.2
  Top Layer w6.16: JP2.24 75,-727.22 75,-594 93,-576 266,-576 322,-520 322,-359.36 U1.34
PC6: JP1.16 U1.63 | length 537.3
  Top Layer w6.16: U1.63 430,383.99 JP1.16
PC7: JP1.15 U1.64 | length 629.1
  Top Layer w6.16: U1.64 388,369.83 388,754.28 JP1.15
PC8: JP1.18 U1.65 | length 499.3
  Top Layer w6.16: U1.65 353.86,363.53 353.86,667.64 330,691.51 JP1.18
PC9: JP1.17 U1.66 | length 609.3
  Top Layer w6.16: U1.66 333.75,371.25 333.75,521.75 333.75,529.25 288,575 288,754.28 JP1.17
PC10: JP1.27 U1.78 | length 497.8
  Top Layer w6.16: JP1.27 -128,754.28 -128,480.39 U1.78
PC11: JP1.28 U1.79 | length 405.9
  Top Layer w6.16: JP1.28 -170,494.55 U1.79
PC12: JP1.29 U1.80 | length 555.5
  Top Layer w6.16: JP1.29 -226,752.28 -226,522.71 U1.80
PC13: JP2.38 U1.7 | length 969.8
  Top Layer w6.16: JP2.38 -668.22,-772.22 -628,-732 -628,-610 -585,-567 -585,-243 -489.04,-147.04 -269.07,-147.04 -235.41,-113.38 U1.7
PC14: C3.2 U1.8 Y2.1 | length 322.3
  Top Layer w5.59: Y2.1 -426.25,-229.03 Y2.1@-411.52,-229.03 ; Y2.1@-420.68,-223.46 Y2.1@-409.07,-223.46 ; U1.8@-241.71,-148.52 U1.8
  Top Layer w10: Y2.1 -435.41,-223.46 -420.68,-223.46 Y2.1@-426.25,-229.03 ; Y2.1@-409.07,-223.46 -393.06,-239.47 -384.78,-239.47 -369.87,-224.56 -369.87,-214.69 -369.87,-208.92 C3.2 C3.2@-367.09,-206.14 ; C3.2@-363.02,-206.14 -360.38,-208.78 -352.09,-208.78 -304.43,-161.12 -251.3,-161.12 -241.71,-151.52 U1.8@-241.71,-148.52
PC15: C4.2 U1.9 Y2.2 | length 309.7
  Top Layer w5.59: Y2.2 Y2.2@-363.03,-287.16 ; Y2.2@-357.46,-301.41 Y2.2@-357.46,-275.07
  Top Layer w10: Y2.2 Y2.2@-357.46,-301.41 ; Y2.2@-357.46,-275.07 -373.47,-259.06 -373.47,-250.78 -359.55,-236.86 -346.11,-236.86 -339.91,-236.86 -338.93,-235.88 C4.2 -338.14,-235.09 -337.13,-234.08 -337.13,-230.02 -338.14,-229.01 -339.77,-227.37 -339.77,-219.09 -297.8,-177.12 -244.67,-177.12 -230,-162.44 -227.79,-162.44 U1.9
PD0: JP1.30 U1.81 | length 463.7
  Top Layer w6.16: JP1.30 -266.56,692.85 -266.56,535.44 U1.81
PD1: JP1.31 U1.82 | length 613.2
  Top Layer w6.16: JP1.31 -315,741.28 -315,556.03 U1.82
PD2: JP1.32 U1.83 | length 521.4
  Top Layer w6.16: JP1.32 -370,583.19 U1.83
PD3: JP1.33 U1.84 | length 671
  Top Layer w6.16: JP1.33 -423,749.28 -423,608.36 U1.84
PD4: JP1.34 U1.85 | length 579.1
  Top Layer w6.16: JP1.34 -470,627.52 U1.85
PD5: JP1.35 U1.86 | length 728.7
  Top Layer w6.16: JP1.35 -520,746.28 -520,649.68 U1.86
PD6: JP1.36 U1.87 | length 636.8
  Top Layer w6.16: JP1.36 -559.58,685.86 -559.58,661.42 U1.87
PD7: JP1.37 U1.88 | length 806.8
  Top Layer w6.16: JP1.37 -620,746.28 -620,659.16 -606.84,646 -572,646 U1.88
PD8: JP1.8 U1.55 | length 768.2
  Top Layer w6.16: U1.55 830,561.28 JP1.8
PD9: JP1.7 U1.56 | length 860.1
  Top Layer w6.16: U1.56 779,538.12 779,745.28 JP1.7
PD10: JP1.10 U1.57 | length 710.5
  Top Layer w6.16: U1.57 730,516.96 JP1.10
PD11: JP1.9 U1.58 | length 802.3
  Top Layer w6.16: U1.58 682,496.8 682,748.28 JP1.9
PD12: JP1.12 U1.59 | length 652.8
  Top Layer w6.16: U1.59 630,472.64 JP1.12
PD13: JP1.11 U1.60 | length 744.6
  Top Layer w6.16: U1.60 589.42,459.9 589.42,755.71 JP1.11
PD14: JP1.14 U1.61 | length 598.3
  Top Layer w6.16: U1.61 534,432.31 534,692.28 JP1.14
PD15: JP1.13 U1.62 | length 686.9
  Top Layer w6.16: U1.62 476,402.15 476,742.28 JP1.13
PE0: JP2.43 KEY.1 R11.2 U1.97 | length 1435.8
  Top Layer w6.16: JP2.43 -970,-601 -924,-555 -924,-370 -817,-263 KEY.1 -810.23,-212.23 -782.23,-212.23 -759,-189 -759,39.8 -641.8,157 -537,157 -467,227 -439,227 -393,181 -372,181 -365.53,187.47 R11.2 -361.48,184.93 U1.97
PE1: JP2.44 U1.98 | length 1445.5
  Top Layer w6.16: JP2.44 -921,-723.22 -921,-661 -746.84,-486.84 -746.84,34.77 -641.53,140.08 -434.62,140.08 -406.62,168.08 -376.28,168.08 -376.04,167.84 -372.23,167.84 U1.98
PE2: JP2.41 U1.1 | length 987.6
  Top Layer w6.16: JP2.41 -859.47,-661.69 -859.47,-637.47 -714.98,-492.98 -714.98,-227.98 -561,-74 -362.06,-74 U1.1
PE3: JP2.42 U1.2 | length 1081.1
  Top Layer w6.16: JP2.42 -822,-724.22 -822,-637 -691.13,-506.13 -691.13,-229.13 -550.39,-88.39 -348.61,-88.39 U1.2
PE4: JP2.39 U1.3 | length 931.5
  Top Layer w6.16: JP2.39 -769,-671.22 -769,-623.32 -669,-523.32 -669,-234.84 -536.47,-102.31 -334.69,-102.31 U1.3
PE5: JP2.40 U1.4 | length 1023.4
  Top Layer w6.16: JP2.40 -718,-720.22 -718,-612 -644,-538 -644,-237.68 -522.55,-116.23 -320.77,-116.23 U1.4
PE6: JP2.37 U1.5 | length 873.8
  Top Layer w6.16: JP2.37 -670,-608 -613,-551 -613,-234.52 -508.63,-130.15 -306.85,-130.15 U1.5
PE7: JP2.19 U1.38 | length 597.9
  Top Layer w6.16: JP2.19 240.87,-661.35 261.65,-661.35 383.68,-539.32 383.68,-309.68 U1.38
PE8: JP2.18 U1.39 | length 702.4
  Top Layer w6.16: U1.39 312.05,-210.21 403.37,-301.53 403.37,-536.83 289.42,-650.77 289.42,-731.64 JP2.18
PE9: JP2.17 U1.40 | length 593.2
  Top Layer w6.16: U1.40 376.34,-246.66 423.05,-293.38 423.05,-579.17 JP2.17
PE10: JP2.16 U1.41 | length 710.2
  Top Layer w6.16: U1.41 442.74,-285.22 442.74,-589.26 389,-643 389,-688.6 430,-729.6 JP2.16
PE11: JP2.15 U1.42 | length 600.7
  Top Layer w6.16: U1.42 462.43,-277.07 462.43,-639.8 JP2.15
PE12: JP2.14 U1.43 | length 723.4
  Top Layer w6.16: U1.43 489.42,-276.23 489.42,-731.64 JP2.14
PE13: JP2.13 U1.44 | length 631.6
  Top Layer w6.16: U1.44 510,-268.97 510,-636.84 530,-656.84 JP2.13
PE14: JP2.12 U1.45 | length 781.1
  Top Layer w6.16: U1.45 534.37,-265.5 534.37,-610.37 576.75,-652.75 576.75,-718.97 JP2.12
PE15: JP2.11 U1.46 | length 689.3
  Top Layer w6.16: U1.46 554.06,-257.34 554.06,-596.28 JP2.11
PH0: C1.2 R1.1 U1.12 Y1.1 | length 358.9
  Top Layer w10: Y1.1@-348.61,-405.72 -298.97,-405.72 -287.48,-394.23 -256.36,-363.11 -256.36,-360.95 -241.44,-346.02 -241.44,-337.74 -242.3,-336.88 -242.3,-332.81 C1.2 -239.52,-330.03 -235.45,-330.03 -233.06,-332.42 -224.78,-332.42 -210.58,-318.23 -210.03,-318.23 -204.13,-312.33 -204.13,-304.05 -204.82,-303.35 -204.82,-299.29 R1.1 -199.37,-297.89 -195.4,-293.93 -192.26,-293.93 -186.41,-288.07 -186.41,-273.59 -202.21,-257.79 -202.21,-220.38 U1.12
PH1: C2.2 R1.2 U1.13 Y1.3 | length 295.6
  Top Layer w5.59: C2.2@-217.16,-356.84 C2.2@-215.6,-358.4
  Top Layer w10: Y1.3 -243.54,-389.13 -245.2,-387.47 -245.2,-379.18 -237.1,-371.09 -237.1,-368.93 -228.32,-360.14 -220.03,-360.14 -218.41,-361.76 -214.35,-361.76 -213.29,-360.7 C2.2 -211.56,-358.97 -211.56,-354.91 -213.96,-352.52 -213.96,-344.23 -203.96,-334.23 -203.4,-334.23 -192.82,-323.65 -184.53,-323.65 -183.84,-324.34 -179.77,-324.34 R1.2 -176.99,-321.56 -176.99,-317.49 -177.68,-316.8 -177.68,-301.98 -170.41,-294.7 -170.41,-266.97 -186.21,-251.16 -186.21,-232.9 -172.67,-219.36 -172.67,-219.17 -150.89,-197.39 U1.13
VBAT: JP1.6 U1.6 | length 143.7
  Top Layer w10: U1.6 -247.89,-99.46 -196.43,-48 v1(-196,-48) ; JP1.6 931,695.28 931,628 v1(932,627)
VCAP_1: C6.2 U1.49 | length 114.8
  Top Layer w10: U1.49 476.23,-96 487,-96 C6.2 ; C6.2@503.62,-119.33 C6.2@504.48,-118.47
VCAP_2: C7.2 U1.73 | length 108
  Top Layer w12: U1.73 131.83,364.08 207.23,439.48 C7.2
VCC: D1.1 USART.1 USB.1 | length 198.5
  Top Layer w12: D1.1 897.42,-411 911.73,-396.69 911.73,-384.27 919,-377 919,-370.3 950.3,-339 USB.1
  other v1: 902,-449 934,-418.32 902,-414.5 934,-385 902,-380 934,-351.68 927,156 966,156 966,202 927,203 927,244 966,244
VDDA: C13.2 JP2.4 R5.1 R6.1 U1.22 | length 1712.8
  Top Layer w12: U1.22 -25.48,-322.17 4.4,-292.3 27.7,-292.3 v1(30,-290) ; R6.1@961.64,-583.36 R6.1 R5.1 1102.72,-583.72 v1(1106,-587) 1106,-616 1082,-640 1082,-720.22 JP2.4
  Bottom Layer w12: v1(30,-290) 30,-292.43 50,-312.43 50,-384 289,-623 946,-623 981,-658 981,-723.22 JP2.4
VREF+: JP2.5 R6.2 U1.21 | length 166.3
  Top Layer w12: U1.21 4.58,-264.14 4.58,-258.17 v1(6.88,-255.88) ; v1(878,-574) 903.71,-548.29 R6.2
pads on no net: U2.4 U2.5 U2.6 U3.4 USART.0 USART.4 USB.0 USB.4

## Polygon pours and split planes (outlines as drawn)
GND on Bottom Layer "GND_L04_P000" (solid, remove dead copper, pour order 0): -1472.91,864.09 -1282,1055 1301,1055 1301,-1002 1368,-1069 -1324.42,-1069
GND on Top Layer "GND_L01_P001" (solid, remove dead copper, pour order 1): -1311,1079 1286,1079 1338,1027 1338,-972 -678,-972 -866,-1160 -1464,-562 -1464,-420
3V3 on POWER03 (split plane): 1149.02,575.56 966,575.56 964.04,575.31 962.22,574.55 960.65,573.35 951.65,564.35 876.65,489.35 875.45,487.78 875.14,487.03 874.69,485.96 874.44,484 874.44,279 874.44,118 874.69,116.04 875.14,114.97 875.45,114.22 876.65,112.65 902.65,86.65 904.22,85.45 904.97,85.14 906.04,84.69 908,84.44 961.87,84.44 974.44,71.87 974.44,-246.87 864.65,-356.65 863.45,-358.22 863.14,-358.97 862.69,-360.04 862.44,-362 862.44,-471 862.69,-472.96 863.14,-474.03 863.45,-474.78 864.65,-476.35 870.65,-482.35 872.22,-483.55 874.04,-484.31 876,-484.56 1149.02,-484.56 1149.02,-795.76 995.56,-795.76 995.56,-616 995.31,-614.04 994.55,-612.22 993.35,-610.65 923.35,-540.65 921.78,-539.45 921.03,-539.14 919.96,-538.69 918,-538.44 131.13,-538.44 94.56,-501.87 94.56,-211 94.31,-209.04 93.55,-207.22 92.35,-205.65 90.78,-204.45 88.96,-203.69 87,-203.44 -22,-203.44 -23.96,-203.69 -25.78,-204.45 -27.35,-205.65 -28.55,-207.22 -29.31,-209.04 -29.56,-211 -29.56,-795.76 -974.89,-795.76 -974.89,816.33 1149.02,816.33
VBAT on POWER03 (split plane): 958.44,610.56 519,610.56 517.04,610.31 515.22,609.55 513.65,608.35 -182.13,-87.44 -188.87,-87.44 -226.44,-49.87 -226.44,-42.13 471.13,655.44 958.44,655.44
VREF+ on POWER03 (split plane): 79.44,-505 79.69,-506.96 80.14,-508.03 80.45,-508.78 81.65,-510.35 122.65,-551.35 124.22,-552.55 124.97,-552.86 126.04,-553.31 128,-553.56 914.87,-553.56 980.44,-619.13 980.44,-795.76 -14.44,-795.76 -14.44,-218.56 79.44,-218.56
VCC on POWER03 (split plane): 1149.02,494.87 1146.14,492.26 1141.39,487.02 1137.18,481.34 1133.54,475.27 1130.52,468.87 1128.13,462.21 1126.41,455.35 1125.37,448.35 1125.08,442.39 1125.02,441.29 1125.02,171.13 1125.08,170.02 1125.37,164.06 1126.41,157.07 1128.13,150.2 1130.52,143.54 1133.54,137.15 1137.18,131.08 1141.39,125.4 1146.14,120.16 1149.02,117.55 1149.02,-95.13 1146.14,-97.74 1141.39,-102.98 1137.18,-108.66 1133.54,-114.73 1130.52,-121.13 1128.13,-127.79 1126.41,-134.65 1125.37,-141.65 1125.08,-147.61 1125.02,-148.71 1125.02,-418.87 1125.08,-419.98 1125.37,-425.94 1126.41,-432.93 1128.13,-439.8 1130.52,-446.46 1133.54,-452.85 1137.18,-458.92 1141.39,-464.6 1145.77,-469.44 879.13,-469.44 877.56,-467.87 877.56,-365.13 987.35,-255.35 988.55,-253.78 989.31,-251.96 989.56,-250 989.56,75 989.31,76.96 988.55,78.78 987.35,80.35 970.35,97.35 968.78,98.55 968.03,98.86 966.96,99.31 965,99.56 911.13,99.56 889.56,121.13 889.56,279 889.56,480.87 962.35,553.65 969.13,560.44 1149.02,560.44
GND on GND02 (split plane): -975.93,856.33 -975.92,856.33 1150.06,856.33 1150.55,856.38 1155.15,856.08 1160.16,855.08 1165,853.44 1169.58,851.18 1173.82,848.34 1177.66,844.98 1181.03,841.14 1183.87,836.89 1186.13,832.31 1187.77,827.48 1188.76,822.47 1189.07,817.86 1189.02,817.37 1189.02,472.25 1187.2,471.81 1182.54,469.89 1178.25,467.25 1174.42,463.98 1171.15,460.15 1168.51,455.86 1166.59,451.2 1165.41,446.31 1165.02,441.29 1165.02,171.13 1165.41,166.11 1166.59,161.21 1168.51,156.56 1171.15,152.26 1174.42,148.43 1178.25,145.16 1182.54,142.53 1187.2,140.6 1189.02,140.16 1189.02,-117.75 1187.2,-118.19 1182.54,-120.11 1178.25,-122.75 1174.42,-126.02 1171.15,-129.85 1168.51,-134.14 1166.59,-138.8 1165.41,-143.69 1165.02,-148.71 1165.02,-418.87 1165.41,-423.89 1166.59,-428.79 1168.51,-433.44 1171.15,-437.74 1174.42,-441.57 1178.25,-444.84 1182.54,-447.47 1187.2,-449.4 1189.02,-449.84 1189.02,-796.8 1189.07,-797.29 1188.76,-801.9 1187.77,-806.9 1186.13,-811.74 1183.87,-816.32 1181.03,-820.57 1177.66,-824.41 1173.82,-827.77 1169.58,-830.61 1165,-832.87 1160.16,-834.51 1155.15,-835.51 1150.55,-835.81 1150.06,-835.76 -975.93,-835.76 -976.42,-835.81 -981.02,-835.51 -986.03,-834.51 -990.86,-832.87 -995.44,-830.61 -999.69,-827.77 -1003.53,-824.41 -1006.9,-820.57 -1009.73,-816.32 -1011.99,-811.74 -1013.63,-806.9 -1014.63,-801.9 -1014.93,-797.29 -1014.88,-796.8 -1014.88,817.37 -1014.93,817.86 -1014.63,822.47 -1013.63,827.48 -1011.99,832.31 -1009.73,836.89 -1006.9,841.14 -1003.53,844.98 -999.69,848.34 -995.44,851.18 -990.86,853.44 -986.03,855.08 -981.02,856.08 -976.41,856.38

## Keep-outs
Keep-Out Layer:
  the board outline again, w6

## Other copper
Top Layer:
  pour cut-out: -999.55,-627 976.38,-627 975,-815 969.42,-815 -1004,-809 -1009.17,-653.07
  pour cut-out: -1000.52,843 -1001.55,843 976,843 976,643 964,643 -1011.61,643 -1011.61,823.63
  pour cut-out: -351,-171.08 -302.12,-219.96 -284.04,-219.96 -167,-337 -167,-378 -149.77,-395.23 -276,-521.47 -276,-523 -315,-523 -419,-419 -419,-370.53 -405.23,-356.77 -499.46,-262.54 -499.46,-221 -492.68,-221 -443.52,-171.85 -351.77,-171.85
  pour cut-out: 874,202 876,200 876,-192 909,-225 1053,-225 1056,-228 1056,-249 1044.68,-260.32 801.32,-260.32 796,-255 796,-47 767,-47 759,-39 762,-36 762,51 796,85 796,196 802,202
  region net 5V: 758,-428 750,-435 708,-435 699,-426 699,-173 713,-159 742,-159 750,-151 750,-112 769,-93 769,-41 774,-36 785,-36 790,-109 784,-116 784,-427 776,-435 750,-435
  region net GND: 1056,-247 1055,-248 978,-248 974,-252 972,-252 871,-252 871,-226 874.5,-222.5 878,-226 1054,-226 1056,-228
  region net GND: 802,202 874,202 876,200 876,132 869,125 838,125 833,120 833,114 833,-159 843,-169 872,-169 876,-173 876,-174 876,-247 871,-252 807.43,-252 802,-245.67 802,-230
  region net GND: 805,11 798,4 770,4 763,-3 763,-25 767,-29 797,-29 803,-35 832,-35 838,-29 874,-29 879,-24 879,0 874,5 873,4 837,4 833,8
  region net GND: 802,202 796,196 796,85 803,78
  region net 5V: 785,-36 790,-41 791,-41 791,-108 790,-109
  region net 3V3: 753.25,130.25 766.5,117 780,117 781,116 781,87 760.08,87 751,77 751,28 735,12 690.52,12
  region net 3V3: 756,201 758,199 758,124.05 751.5,125.5 752,85.97 702,12 642,12 632,22 632,176 657,201
  region net VCC: 951,-411 951,-443 929,-465 846,-465 826,-445 826,-402 827,-401 840,-410
  region net VCC: 916,269 1052,269 1055,266 1055,253 1053,251 993,251 985,243 985,149 973,137 917,137 906,148 906,259
  region net VCC: 1040,-331 1055,-331 1057,-333 1057,-345 1055,-347 1025.1,-347 1021,-351.1 1021,-369 954,-369 951,-372 951,-411 931,-431 838,-431 826,-419 826,-385 843,-368 890,-368 926,-332 930,-332
POWER03 (plane layer: these items are gaps in the copper):
  lines w15: 1166,-516 1166,-477 876,-477 870,-471 870,-362 982,-250 982,75 965,92 908,92 882,118 882,279 882,484 957,559 966,568 1169,568 ; -234,-53 -234,-39 468,663 966,663 966,603 519,603 -179,-95 -192,-95 -234,-53 ; -22,-847 -19,-850 640,-850 642,-848 655,-848 663,-856 988,-856 988,-616 918,-546 128,-546 87,-505 87,-211 -22,-211 -22,-847

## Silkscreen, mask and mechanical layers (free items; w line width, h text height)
Top Overlay:
  drawing of 2457 lines, arcs and shapes, not listed
  text "GND" at 1065,646 h15
  text "GND" at 998,634 h15
  text "5V" at 1066,624 h15
  text "3V3" at 999,612 h15
  text "PB8" at -1008.59,605.93 h40
  text "PB6" at -908.51,605.93 h40
  text "PB4" at -808.44,605.93 h40
  text "PD7" at -709.38,605.93 h40
  text "PD5" at -609.42,605.57 h40
  text "PD3" at -509.27,605.57 h40
  text "PD1" at -409.17,605.93 h40
  text "PC12" at -318.96,605.57 h40
  text "PC10" at -218.99,605.57 h40
  text "PA15" at -118.09,605.93 h40
  text "PA13" at -17.94,605.57 h40
  text "PA11" at 84.58,605.93 h40
  text "PA9" at 192.07,605.93 h40
  text "PC9" at 291.15,605.57 h40
  text "PC7" at 384.75,605.57 h40
  text "PD15" at 481.26,605.91 h40
  text "PD13" at 581.41,605.91 h40
  text "PD11" at 683.93,605.93 h40
  text "PD9" at 782.5,605.91 h40
  text "PB15" at 884.41,603.91 h40
  text "PB9" at -1008.59,570.93 h40
  text "PB7" at -908.51,570.91 h40
  text "PB5" at -808.55,571.02 h40
  text "PB3" at -709.38,570.91 h40
  text "PD6" at -609.33,570.57 h40
  text "PD4" at -509.27,570.55 h40
  text "PD2" at -409.09,571.35 h40
  text "PD0" at -309.12,570.91 h40
  text "PC11" at -216.57,570.57 h40
  text "PA14" at -117.95,571.35 h40
  text "PA12" at -17.81,570.57 h40
  text "PA10" at 82.16,570.93 h40
  text "PA8" at 192.07,570.93 h40
  text "PC8" at 291.15,570.57 h40
  text "PC6" at 385,570.57 h40
  text "PD14" at 481.4,571.35 h40
  text "PD12" at 581.53,571.35 h40
  text "PD10" at 681.56,570.93 h40
  text "PD8" at 782.63,570.93 h40
  text "VBAT" at 882.81,569.35 h40
  text "CLK" at -698,481 h60
  text "DIO" at -698,381 h60
  text "GND" at -698,281 h60
  text "3V3" at -698,181 h60
  text "CDUT-ZHR" at -1010,41 h60
  text "PE0" at -1005.55,-586.07 h40
  text "PE2" at -905.49,-586.07 h40
  text "PE4" at -805.44,-586.07 h40
  text "PE6" at -705.4,-586.07 h40
  text "PC0" at -606.28,-586.43 h40
  text "PC2" at -506.15,-586.43 h40
  text "PA0" at -405.22,-586.07 h40
  text "PA2" at -305.16,-586.07 h40
  text "PA4" at -205.11,-586.07 h40
  text "PA6" at -105.06,-586.07 h40
  text "PC4" at -5.95,-586.43 h40
  text "PB1" at 95.06,-586.07 h40
  text "PE7" at 195.1,-586.07 h40
  text "PE9" at 295.13,-586.07 h40
  text "PE11" at 387.75,-586.07 h40
  text "PE13" at 485.34,-586.09 h40
  text "PE15" at 585.3,-586.07 h40
  text "PB11" at 687.91,-586.07 h40
  text "PB13" at 785.5,-586.09 h40
  text "VREF" at 889,-595 h15
  text "5V" at 1138,-603 h15
  text "PB14" at 890,-617 h15
  text "PE1" at -1005.55,-620.65 h40
  text "PE3" at -905.51,-621.09 h40
  text "PE5" at -805.55,-620.98 h40
  text "PC13" at -716.31,-621.45 h40
  text "PC1" at -605.33,-621.43 h40
  text "PC3" at -506.27,-621.45 h40
  text "PA1" at -405.22,-620.65 h40
  text "PA3" at -305.18,-621.09 h40
  text "PA5" at -205.22,-620.98 h40
  text "PA7" at -105.06,-620.65 h40
  text "PC5" at -6.09,-621.43 h40
  text "PB0" at 95.06,-621.07 h40
  text "PB2" at 195.12,-620.65 h40
  text "PE8" at 295.13,-621.07 h40
  text "PE10" at 385.32,-621.07 h40
  text "PE12" at 485.46,-620.65 h40
  text "PE14" at 585.44,-620.65 h40
  text "PB10" at 685.49,-621.07 h40
  text "PB12" at 785.63,-620.65 h40
  text "3V3" at 958,-621 h15
  text "GND" at 1139,-625 h15
  text "GND" at 959,-643 h15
